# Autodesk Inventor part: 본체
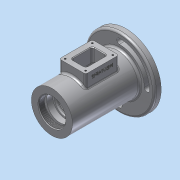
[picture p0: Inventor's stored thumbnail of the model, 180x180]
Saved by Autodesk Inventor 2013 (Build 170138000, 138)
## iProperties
Created: 2017-05
Part Number: 본체
Material: 알루미늄 6061
Document SubType Name: Modeling
Designer: dgall
Density: 2.71 g/cm^3
Mass: 720.141 g
Surface Area: 631.027 cm^2
Volume: 265.735 cm^3
Author: dgall
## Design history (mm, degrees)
revolve "회전1" stored, may be unused: angle "d8" = 90 deg
revolve "회전2" stored, may be unused: angle "d37" = 90 deg
node "작업 평면1"
sketch "스케치2"
  geometry: L1 (-81, -20)-(-31, -20); L2 (-31, -20)-(-31, 20); L3 (-31, 20)-(-81, 20); L4 (-81, 20)-(-81, -20); 3 further points
  constraints: 8 end point, 2 midpoint, 2 parallel, 1 horizontal, 1 horizontal alignment, 1 perpendicular
  dimensions: "d39" = 50 distance of L3.end L2.end; "d40" = 40 distance of L2.end L1.end; "d41" = 56 horizontal distance of point (0, 0) point (-56, -20)
extrude "돌출1" join sketch "스케치2" stored distance "d42" = 10; taper "d43" = 0 deg
sketch "스케치3"
  geometry: L1 (81, 20)-(31, 20) reference; L2 (40, -11)-(72, -11); L3 (72, -11)-(72, 11); L4 (72, 11)-(40, 11); L5 (40, 11)-(40, -11); 4 further points
  constraints: 8 end point, 3 midpoint, 2 parallel, 1 horizontal, 1 horizontal alignment, 1 perpendicular, 1 vertical alignment
  dimensions: "d49" = 32 distance of L4.end L3.end; "d50" = 22 distance of L3.end L2.end
extrude "돌출2" cut sketch "스케치3" distance "d51" = 50; taper "d52" = 0 deg
fillet "모깎기1" dims "d53" = 3
fillet "모깎기2" dims "d54" = 3
sketch "스케치4"
  geometry: L1 (43, 11)-(69, 11) reference; 4 further points
  constraints: 2 midpoint, 1 coincident
  dimensions: "d55" = 15.5 vertical distance of point (0, 0) point (35.5, 15.5); "d56" = 20.5 horizontal distance of point (35.5, 15.5) point (56, 11)
hole "구멍1" sketch "스케치4" at (35.5, 15.5) diameter "d57" = 2.621; stored, may be unused: countersink angle "d61" = 90 deg, drill point angle "d63" = 118 deg; dims "d58" = 6, "d59" = 4, "d60" = 2, "d62" = 8
sketch "스케치6"
  geometry: C1 r 31 at (0, 0) reference; C2 r 53 at (0, 0) reference; A1 r 37.5 centre (0, 0) between (0, 37.5) and (-37.5, 0); A2 r 45.5 centre (0, 0) between (0, 45.5) and (-45.5, 0); A3 r 4 centre (-41.5, 0) between (-45.5, 0) and (-37.5, 0); A4 r 4 centre (0, 41.5) between (0, 37.5) and (0, 45.5); A5 r 37.5 centre (0, 0) between (0, -37.5) and (37.5, 0); A6 r 45.5 centre (0, 0) between (0, -45.5) and (45.5, 0); A7 r 4 centre (0, -41.5) between (0, -37.5) and (0, -45.5); A8 r 4 centre (41.5, 0) between (45.5, 0) and (37.5, 0)
  constraints: 16 point on circle, 8 centre point, 8 tangent, 4 coincident, 2 concentric, 2 horizontal alignment, 2 vertical alignment
  dimensions: "d70" = 37.5 radius of A1; "d73" = 45.5 radius of A2
extrude "돌출3" cut sketch "스케치6" stored distance "d74" = 10; taper "d75" = 0 deg
fillet "모깎기3" dims "d76" = 3
hole "구멍2" diameter "d80" = 40.376; stored, may be unused: countersink angle "d84" = 90 deg, drill point angle "d86" = 0 deg; dims "d78" = 10, "d79" = 10, "d81" = 6, "d82" = 4, "d83" = 2, "d85" = 9
chamfer "모따기1" distance "d87" = 1; stored, may be unused: second distance "d88" = 2, angle "d89" = 45 deg
fillet "모깎기4" dims "d90" = 3
sketch "스케치7"
  geometry: L1 (0, 0)-(44, 0) reference; L2 (-34, -75)-(-34, -13) reference; 2 further points
  constraints: 1 other
  dimensions: "d91" = 56 distance from line of L2 point (22, -8); "d92" = 8 distance from line of L1 point (22, -8)
feature "엠보싱1" sketch "스케치7" dims "d93" = 0.5, "d94" = 0
chamfer "모따기2" distance "d97" = 1; stored, may be unused: second distance "d98" = 2, angle "d99" = 45 deg
node "솔리드1"
sketch "스케치1"
  geometry: L1 (0, 0)-(115, 0); L2 (0, 0)-(0, 31); L3 (0, 31)-(102, 31); L4 (102, 31)-(102, 53); L5 (102, 53)-(112, 53); L6 (112, 53)-(112, 31); L7 (112, 31)-(115, 31); L8 (115, 31)-(115, 0); L9 (9, 21)-(9, 24); L10 (9, 24)-(12, 24); L11 (12, 24)-(12, 20); L12 (12, 20)-(21, 20); L13 (21, 20)-(21, 17.5); L14 (21, 17.5)-(24.25, 17.5); L15 (24.25, 17.5)-(24.25, 18.5); L16 (24.25, 18.5)-(26, 18.5); L17 (26, 18.5)-(26, 17.5); L18 (26, 17.5)-(36, 17.5); L19 (37, 18.5)-(37, 23); L20 (40, 26)-(72, 26); L21 (75, 23)-(75, 18.5); L22 (76, 17.5)-(85.7, 17.5); L23 (86, 17.2)-(86, 16.5); L24 (86, 16.5)-(88, 16.5); L25 (91, 13.5)-(91, 10); L26 (91, 10)-(93.7, 10); L27 (93.7, 10)-(93.7, 12.2); L28 (94, 12.5)-(100.3, 12.5); L29 (100.3, 12.5)-(101, 12.904); L30 (101, 12.904)-(101, 14.022); L31 (102.818, 16.779)-(115, 22); L32 (37, 18.5)-(36, 17.5); L33 (75, 18.5)-(76, 17.5); L34 (9, 21)-(9, 0); A1 r 0.3 centre (94, 12.2) between (94, 12.5) and (93.7, 12.2); A2 r 0.3 centre (85.7, 17.2) between (86, 17.2) and (85.7, 17.5); A3 r 3 centre (40, 23) between (40, 26) and (37, 23); A4 r 3 centre (72, 23) between (75, 23) and (72, 26); A5 r 3 centre (88, 13.5) between (91, 13.5) and (88, 16.5); A6 r 3 centre (104, 14.022) between (102.818, 16.779) and (101, 14.022); 8 further points
  constraints: 68 end point, 18 point on line, 13 parallel, 12 point on circle, 12 tangent, 8 perpendicular, 6 centre point, 3 equal radius, 3 horizontal alignment, 2 collinear, 2 horizontal, 2 vertical
  dimensions: "d0" = 115 distance of L1.start L1.end; "d1" = 62 diameter of L3 L1; "d3" = 106 diameter of L5 L1; "d6" = 3 distance of L6.end L7.end; "d10" = 48 diameter of L10 L1; "d11" = 40 diameter of L12 L1; "d13" = 35 diameter of L14 L1; "d14" = 3 distance of L9.end L10.end; "d16" = 21 distance between parallel lines of L2 L13; "d18" = 1.75 distance of L15.end L16.end; "d19" = 37 diameter of L16 L1; "d20" = 11 distance of L17.end point (37, 17.5); "d21" = 52 diameter of L20 L1; "d22" = 11 distance of point (75, 17.5) point (86, 17.5); "d23" = 33 diameter of L24 L1; "d24" = 20 diameter of L26 L1; "d25" = 5 distance of L23.end point (91, 16.5); "d26" = 2.7 distance of L25.end L26.end; "d27" = 25 diameter of L28 L1; "d29" = 0.7 horizontal distance of L28.end L29.end; "d30" = 30 deg angle of L28 L29; "d31" = 32 diameter of point (101, 16) L1; "d33" = 44 diameter of L31.end L1; "d34" = 14 horizontal distance of point (101, 16) L31.end; "d35" = 0.3 radius of A1; "d36" = 0.3 radius of A2; "d44" = 3 radius of A3; "d45" = 1 distance of L19.start point (37, 17.5); "d46" = 1 distance of L18.end point (37, 17.5) (= d45); "d47" = 1 distance of L21.end point (75, 17.5) (= d45); "d48" = 1 distance of L22.start point (75, 17.5) (= d47); "d77" = 12 distance between parallel lines of L2 L11; "d95" = 38 distance between parallel lines of L21 L19; "d96" = 26 distance from line of L2 L17.end; "d100" = 13 horizontal distance of L7.end L4.end
pattern_linear "직사각형 패턴1" dims "d66" = 41, "d69" = 31
other parameters: "d38" = 44
